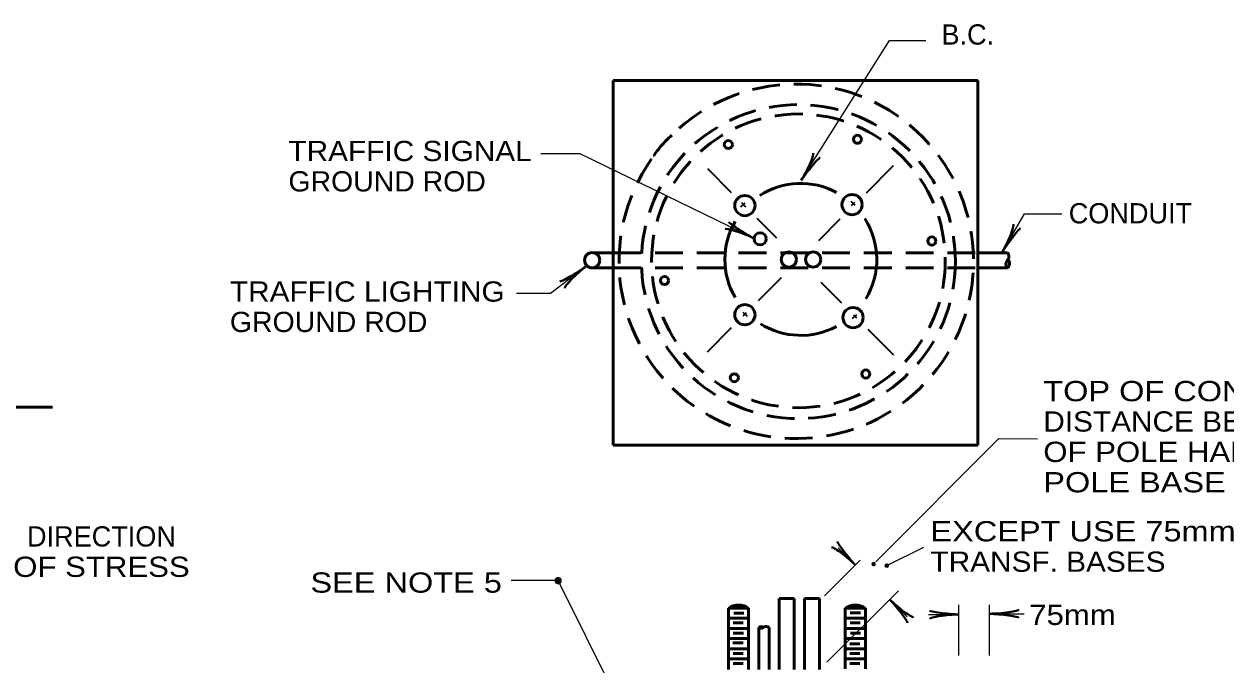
# Model space of a CAD drawing. Extents: x -711 to 145, y 25 to 569.
# Drawn here: x -395 to -252.6, y 170 to 246 of the extents above; entities that cross this region are included whole.
import ezdxf
from ezdxf.enums import TextEntityAlignment as Align

# ---------------------------------------------------------------- set-up
doc = ezdxf.new("R2010")
doc.units = 0
doc.header["$LTSCALE"] = 1.1
doc.header["$PDMODE"] = 32
doc.header["$PDSIZE"] = 0.55
doc.linetypes.add('MEDIUM_DASHED', pattern=[4.5, 3, -1.5])
doc.layers.add('1', color=7, linetype='Continuous', lineweight=53)

msp = doc.modelspace()

# ---------------------------------------------------------------- linework, layer by layer
at = {"layer": '1'}
for p, q in [((-325.189, 239.263), (-325.189, 196.063)), ((-325.189, 239.263), (-281.989, 239.263)), ((-281.989, 239.263), (-281.989, 196.063)), ((-327.602, 218.863), (-325.202, 218.863)), ((-282.083, 218.857), (-278.483, 218.857)), ((-327.597, 217.068), (-325.197, 217.068)), ((-282.072, 217.057), (-278.472, 217.057)), ((-465.3, 200.556), (-391.648, 200.556)), ((-325.189, 196.063), (-281.989, 196.063)), ((-311.546, 176.743), (-311.546, 169.492)), ((-311.546, 176.743), (-309.146, 176.743)), ((-309.146, 176.743), (-309.146, 169.492)), ((-305.538, 177.881), (-305.538, 169.481)), ((-305.538, 177.881), (-303.738, 177.881)), ((-303.738, 177.881), (-303.738, 169.481)), ((-302.538, 177.881), (-302.538, 169.481)), ((-302.538, 177.881), (-300.738, 177.881)), ((-300.738, 177.881), (-300.738, 169.481)), ((-297.708, 176.743), (-297.708, 169.543)), ((-297.708, 176.743), (-295.308, 176.743)), ((-295.308, 176.743), (-295.308, 169.543)), ((-311.546, 175.543), (-309.146, 175.543)), ((-310.901, 176.159), (-309.701, 176.159)), ((-297.708, 175.543), (-295.308, 175.543)), ((-297.106, 176.182), (-295.906, 176.182)), ((-311.546, 174.343), (-309.146, 174.343)), ((-310.991, 174.989), (-309.791, 174.989)), ((-310.968, 173.796), (-309.768, 173.796)), ((-307.923, 174.46), (-307.923, 169.492)), ((-307.316, 174.51), (-307.354, 174.475)), ((-306.723, 174.46), (-306.723, 169.492)), ((-297.708, 174.343), (-295.308, 174.343)), ((-297.128, 174.989), (-295.928, 174.989)), ((-297.083, 173.774), (-295.883, 173.774)), ((-311.546, 173.143), (-309.146, 173.143)), ((-311.013, 172.626), (-309.813, 172.626)), ((-297.708, 173.143), (-295.308, 173.143)), ((-297.173, 172.536), (-295.973, 172.536)), ((-311.546, 171.943), (-309.146, 171.943)), ((-310.991, 171.388), (-309.791, 171.388)), ((-297.708, 171.943), (-295.308, 171.943)), ((-297.151, 171.388), (-295.951, 171.388)), ((-311.546, 170.743), (-309.146, 170.743)), ((-310.991, 170.196), (-309.791, 170.196)), ((-297.708, 170.743), (-295.308, 170.743)), ((-297.173, 170.196), (-295.973, 170.196))]:
    msp.add_line(p, q, dxfattribs=at)
at = {"layer": '1', "lineweight": 35}
for p, q in [((-314.03, 228.824), (-311.218, 226.011)), ((-295.197, 225.965), (-291.965, 229.197)), ((-310.058, 224.296), (-309.563, 224.791)), ((-310.003, 224.796), (-309.508, 224.301)), ((-297.044, 224.976), (-296.549, 224.481)), ((-296.962, 224.47), (-296.568, 224.864)), ((-308.158, 222.952), (-305.85, 220.643)), ((-300.836, 220.326), (-298.302, 222.86)), ((-307.976, 213.186), (-305.245, 215.917)), ((-300.585, 215.378), (-298.124, 212.917)), ((-309.823, 211.837), (-309.328, 211.342)), ((-309.792, 211.37), (-309.387, 211.775)), ((-296.829, 211.066), (-296.334, 211.561)), ((-296.729, 211.523), (-296.369, 211.163)), ((-314.026, 207.135), (-311.171, 209.991)), ((-295.019, 209.813), (-291.969, 206.762))]:
    msp.add_line(p, q, dxfattribs=at)
at = {"layer": '1', "linetype": 'MEDIUM_DASHED'}
for p, q in [((-325.189, 218.863), (-281.989, 218.863)), ((-325.189, 217.063), (-281.989, 217.063))]:
    msp.add_line(p, q, dxfattribs=at)
at = {"layer": '1', "lineweight": 25}
for p, q in [((-298.523, 183.878), (-296.507, 181.862)), ((-292.789, 181.814), (-288.378, 183.974)), ((-300.159, 178.21), (-295.917, 182.453)), ((-331.719, 180.005), (-337.301, 180.005)), ((-317.853, 152.275), (-331.719, 180.005)), ((-299.889, 170.334), (-291.404, 178.819)), ((-292.434, 177.789), (-290.353, 175.708)), ((-284.224, 171.133), (-284.224, 177.133)), ((-280.624, 171.133), (-280.624, 177.133)), ((-287.826, 175.994), (-284.226, 175.994)), ((-280.579, 176.084), (-276.484, 176.084))]:
    msp.add_line(p, q, dxfattribs=at)
for points in [[(-302.916, 227.447), (-292.471, 243.993), (-288.156, 243.993)], [(-308.586, 220.607), (-329.105, 230.597), (-333.786, 230.597)], [(-279.067, 218.987), (-276.457, 223.487), (-272.047, 223.487)], [(-328.475, 217.187), (-332.615, 214.037), (-336.666, 214.037)], [(-294.068, 182.252), (-279.483, 196.837), (-274.914, 196.817)]]:
    msp.add_lwpolyline(points, dxfattribs=at)
at = {"layer": '1', "linetype": 'MEDIUM_DASHED'}
for centre, radius in [((-303.242, 217.813), 18.6), ((-303.242, 217.903), 17.4)]:
    msp.add_circle(centre, radius, dxfattribs=at)
at = {"layer": '1'}
for centre, radius in [((-311.556, 231.677), 0.48), ((-296.256, 232.306), 0.48), ((-309.591, 224.448), 1.2), ((-296.89, 224.562), 1.2), ((-307.776, 220.517), 0.72), ((-287.437, 220.247), 0.48), ((-327.692, 217.974), 0.9), ((-304.383, 218.064), 0.9), ((-301.503, 218.064), 0.9), ((-319.115, 215.567), 0.48), ((-309.591, 211.518), 1.2), ((-296.776, 211.175), 1.2), ((-310.836, 204.048), 0.48), ((-295.267, 204.498), 0.48), ((-294.324, 181.966), 0.0943), ((-292.778, 181.784), 0.0943)]:
    msp.add_circle(centre, radius, dxfattribs=at)
at = {"layer": '1', "linetype": 'MEDIUM_DASHED'}
for centre, radius, start, end in [((-303.501, 217.844), 21, 144.72797, 134.59975), ((-309.962, 223.331), 12.579, 131.18966, 148.13779)]:
    msp.add_arc(centre, radius, start, end, dxfattribs=at)
at = {"layer": '1'}
for centre, radius, start, end in [((-302.961, 218.07), 9, 61.93145, 122.73056), ((-302.961, 218.07), 9, 150.00307, 209.99693), ((-302.961, 218.07), 9, 328.65081, 32.73064), ((-302.961, 218.07), 9, 237.9532, 298.03362), ((-310.346, 174.999), 2.117, 55.47029, 124.52971), ((-296.508, 174.999), 2.117, 55.47029, 124.52971)]:
    msp.add_arc(centre, radius, start, end, dxfattribs=at)
at = {"layer": '1', "lineweight": 40}
for centre, major_axis, ratio, start_param, end_param in [((-302.498, 228.731), (-0.985, -1.912), 0.122415, 0.8963533, 3.1415927), ((-301.984, 228.448), (1.303, 1.67), 0.07063, 6.2823074, 8.5597026), ((-309.684, 221.424), (1.803, -1.112), 0.07063, 3.1407148, 5.41811), ((-278.697, 220.286), (-0.913, -1.948), 0.122415, 0.8963533, 3.1415927), ((-309.908, 220.882), (2.009, -0.769), 0.122415, 0.8963533, 3.1415927), ((-278.173, 220.023), (-1.24, -1.718), 0.07063, 3.1407148, 5.41811), ((-329.699, 216.575), (-1.805, -1.109), 0.07063, 6.2823074, 8.5597026), ((-329.316, 216.13), (1.592, 1.447), 0.122415, 0.8963533, 3.1415927), ((-297.668, 182.554), (1.648, -1.383), 0.122415, 0.8963533, 3.1415927), ((-297.668, 182.554), (1.648, -1.383), 0.122415, 0.8963533, 3.1415927), ((-297.279, 182.993), (1.341, -1.639), 0.07063, 3.1407148, 5.41811), ((-297.279, 182.993), (1.341, -1.639), 0.07063, 3.1407148, 5.41811), ((-291.663, 176.658), (1.341, -1.639), 0.07063, 6.2823074, 8.5597026), ((-291.663, 176.658), (1.341, -1.639), 0.07063, 6.2823074, 8.5597026), ((-291.274, 177.097), (-1.648, 1.383), 0.122415, 0.8963533, 3.1415927), ((-291.274, 177.097), (-1.648, 1.383), 0.122415, 0.8963533, 3.1415927), ((-285.535, 175.663), (2.143, 0.187), 0.122415, 0.8963533, 3.1415927), ((-285.571, 176.248), (2.108, -0.211), 0.07063, 3.1407148, 5.41811), ((-279.235, 175.83), (2.108, -0.211), 0.07063, 6.2823074, 8.5597026), ((-279.27, 176.416), (-2.143, -0.187), 0.122415, 0.8963533, 3.1415927)]:
    msp.add_ellipse(centre, major_axis=major_axis, ratio=ratio, start_param=start_param, end_param=end_param, dxfattribs=at)
at = {"layer": '1'}
for centre, major_axis, ratio, start_param, end_param in [((-277.973, 217.593), (-0.521, -0.52), 0.84388, 4.7124091, 6.3349528), ((-279.002, 218.336), (0.52, 0.521), 0.896364, 4.6732248, 6.2831853), ((-278.918, 217.543), (0.52, 0.521), 0.896364, 4.6732248, 6.2831853), ((-307.61, 174.131), (-0.313, 0.329), 0.942572, 4.8724074, 6.2831853), ((-307.604, 174.792), (-0.313, -0.329), 0.870662, 0, 1.4228014), ((-307.033, 174.131), (0.343, -0.326), 0.960356, 1.5707963, 2.9651466)]:
    msp.add_ellipse(centre, major_axis=major_axis, ratio=ratio, start_param=start_param, end_param=end_param, dxfattribs=at)
msp.add_spline([(-292.8, 181.836), (-292.789, 181.802), (-292.789, 181.78), (-292.778, 181.757), (-292.744, 181.757), (-292.733, 181.757), (-292.744, 181.791), (-292.778, 181.791), (-292.812, 181.791), (-292.823, 181.746), (-292.778, 181.836), (-292.766, 181.802), (-292.766, 181.746), (-292.8, 181.723), (-292.8, 181.802), (-292.778, 181.802), (-292.733, 181.791), (-292.766, 181.836), (-292.812, 181.802), (-292.766, 181.734), (-292.766, 181.825), (-292.778, 181.813), (-292.789, 181.791), (-292.789, 181.847), (-292.766, 181.813), (-292.8, 181.813), (-292.812, 181.802), (-292.778, 181.768)], degree=3, dxfattribs=at)
msp.add_point((-331.719, 180.005), dxfattribs=at)

# ---------------------------------------------------------------- texts
for s, p in [('B.C.', (-286.297, 243.524)), ('CONDUIT', (-271.216, 222.337))]:
    msp.add_text(s, height=2.4, dxfattribs=at).set_placement(p)
for s, width, p in [('TRAFFIC SIGNAL', 1.1, (-363.68, 229.719)), ('GROUND ROD', 1.05, (-363.68, 226.119)), ('TRAFFIC LIGHTING', 1.1, (-370.613, 213.063)), ('GROUND ROD', 1.05, (-370.613, 209.463)), ('TOP OF CONDUIT TO BE 1/2', 1.2, (-274.232, 201.268)), ('DISTANCE BETWEEN BOTTOM', 1.1, (-274.232, 197.668)), ('OF POLE HANDHOLE AND', 1.15, (-274.232, 194.068)), ('POLE BASE P', 1.2, (-274.232, 190.468)), ('EXCEPT USE 75mm WHEN USING', 1.2, (-287.602, 184.657)), ('TRANSF. BASES', 1.1, (-287.602, 181.057)), ('SEE NOTE 5', 1.2, (-361.069, 178.581)), ('75mm', 1.15, (-275.898, 174.754))]:
    msp.add_text(s, height=2.4, dxfattribs=dict(at, width=width)).set_placement(p)
msp.add_text('DIRECTION', height=2.4, dxfattribs=at).set_placement((-385.834, 184.05), align=Align.CENTER)
at = {"layer": '1', "width": 1.15}
msp.add_text('OF STRESS', height=2.4, dxfattribs=at).set_placement((-385.834, 180.45), align=Align.CENTER)

doc.saveas('drawing.dxf')
